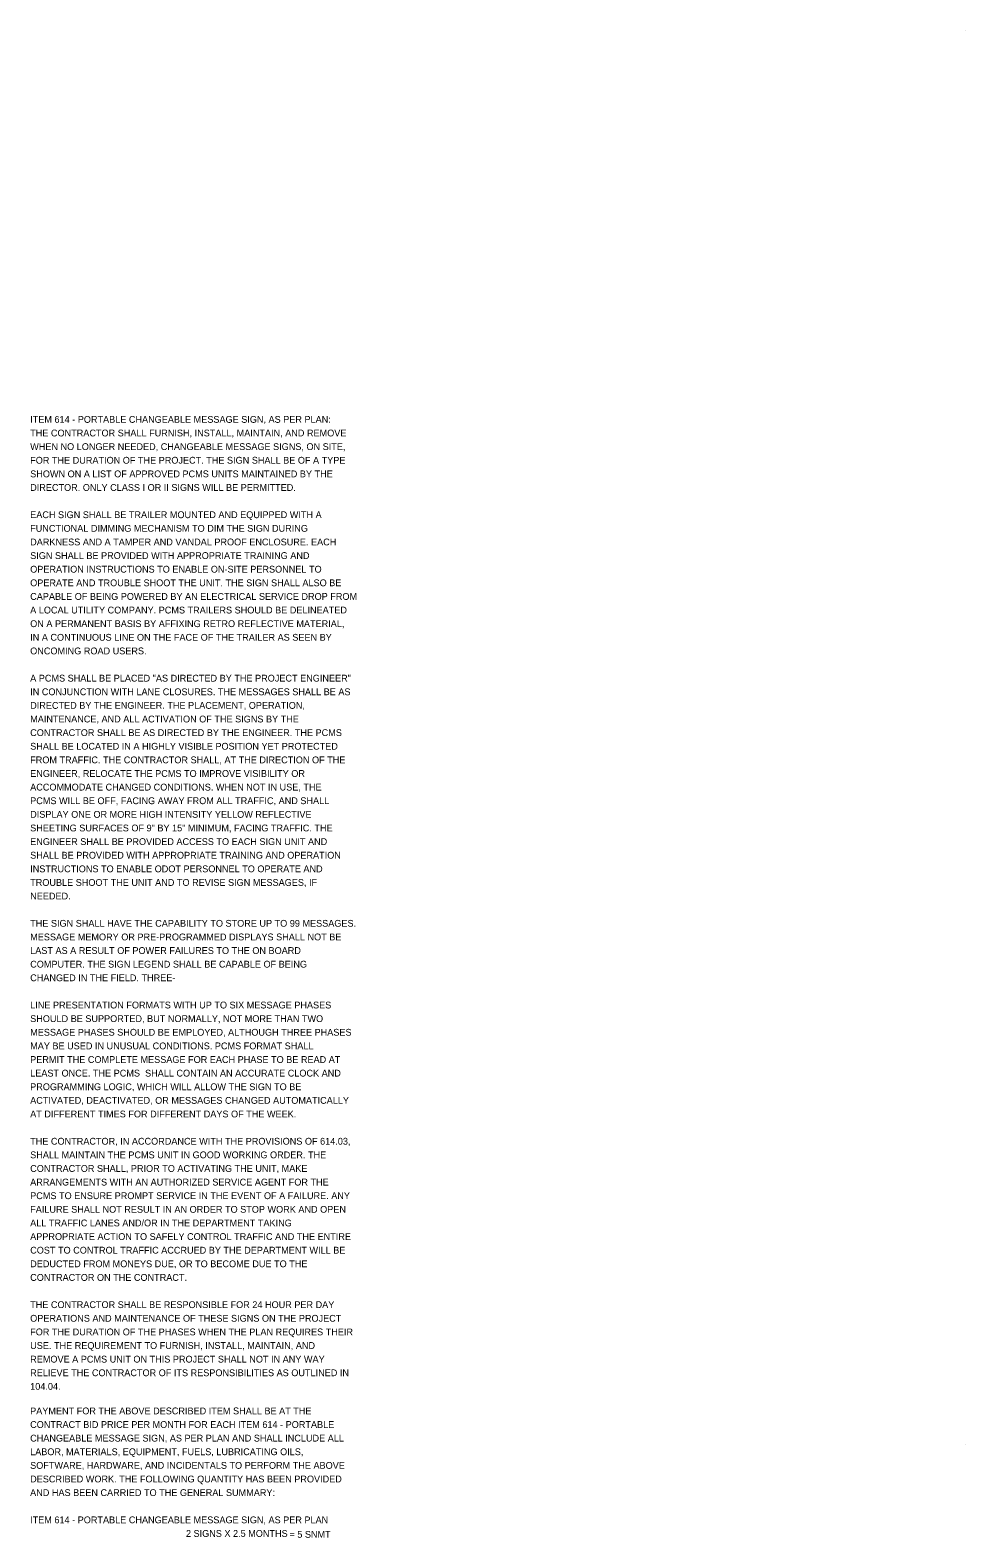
# Model space of a CAD drawing. Extents: x 37613.4 to 37668.4, y 18853.7 to 18946.8.
# Drawn here: x 37617.17 to 37636.4, y 18865.55 to 18896.54 of the extents above; entities that cross this region are included whole.
import ezdxf

# ---------------------------------------------------------------- set-up
doc = ezdxf.new("R2010")
doc.units = 0
doc.layers.add('SH_Data', color=7, linetype='Continuous')
doc.layers.add('SH_Text', color=7, linetype='Continuous')

msp = doc.modelspace()

# ---------------------------------------------------------------- linework, layer by layer
at = {"layer": 'SH_Data'}
for p, q in [((37636.401, 18896.542), (37636.401, 18896.542)), ((37636.401, 18867.47), (37636.401, 18867.47))]:
    msp.add_line(p, q, dxfattribs=at)

# ---------------------------------------------------------------- texts
at = {"layer": 'SH_Text'}
for s, p in [('ITEM 614 - PORTABLE CHANGEABLE MESSAGE SIGN, AS PER PLAN:', (37617.166, 18888.47)), ('THE CONTRACTOR SHALL FURNISH, INSTALL, MAINTAIN, AND REMOVE ', (37617.166, 18888.19)), ('WHEN NO LONGER NEEDED, CHANGEABLE MESSAGE SIGNS, ON SITE, ', (37617.166, 18887.91)), ('FOR THE DURATION OF THE PROJECT. THE SIGN SHALL BE OF A TYPE ', (37617.166, 18887.63)), ('SHOWN ON A LIST OF APPROVED PCMS UNITS MAINTAINED BY THE ', (37617.166, 18887.35)), ('DIRECTOR. ONLY CLASS I OR II SIGNS WILL BE PERMITTED.', (37617.166, 18887.07)), ('EACH SIGN SHALL BE TRAILER MOUNTED AND EQUIPPED WITH A ', (37617.166, 18886.51)), ('FUNCTIONAL DIMMING MECHANISM TO DIM THE SIGN DURING ', (37617.166, 18886.23)), ('DARKNESS AND A TAMPER AND VANDAL PROOF ENCLOSURE. EACH ', (37617.166, 18885.95)), ('SIGN SHALL BE PROVIDED WITH APPROPRIATE TRAINING AND ', (37617.166, 18885.67)), ('OPERATION INSTRUCTIONS TO ENABLE ON-SITE PERSONNEL TO ', (37617.166, 18885.39)), ('OPERATE AND TROUBLE SHOOT THE UNIT. THE SIGN SHALL ALSO BE ', (37617.166, 18885.11)), ('CAPABLE OF BEING POWERED BY AN ELECTRICAL SERVICE DROP FROM ', (37617.166, 18884.83)), ('A LOCAL UTILITY COMPANY. PCMS TRAILERS SHOULD BE DELINEATED ', (37617.166, 18884.55)), ('ON A PERMANENT BASIS BY AFFIXING RETRO REFLECTIVE MATERIAL, ', (37617.166, 18884.27)), ('IN A CONTINUOUS LINE ON THE FACE OF THE TRAILER AS SEEN BY ', (37617.166, 18883.99)), ('ONCOMING ROAD USERS.', (37617.166, 18883.71)), ('A PCMS SHALL BE PLACED "AS DIRECTED BY THE PROJECT ENGINEER" ', (37617.166, 18883.15)), ('IN CONJUNCTION WITH LANE CLOSURES. THE MESSAGES SHALL BE AS ', (37617.166, 18882.87)), ('DIRECTED BY THE ENGINEER. THE PLACEMENT, OPERATION, ', (37617.166, 18882.59)), ('MAINTENANCE, AND ALL ACTIVATION OF THE SIGNS BY THE ', (37617.166, 18882.31)), ('CONTRACTOR SHALL BE AS DIRECTED BY THE ENGINEER. THE PCMS ', (37617.166, 18882.03)), ('SHALL BE LOCATED IN A HIGHLY VISIBLE POSITION YET PROTECTED ', (37617.166, 18881.75)), ('FROM TRAFFIC. THE CONTRACTOR SHALL, AT THE DIRECTION OF THE ', (37617.166, 18881.47)), ('ENGINEER, RELOCATE THE PCMS TO IMPROVE VISIBILITY OR ', (37617.166, 18881.19)), ('ACCOMMODATE CHANGED CONDITIONS. WHEN NOT IN USE, THE ', (37617.166, 18880.91)), ('PCMS WILL BE OFF, FACING AWAY FROM ALL TRAFFIC, AND SHALL ', (37617.166, 18880.63)), ('DISPLAY ONE OR MORE HIGH INTENSITY YELLOW REFLECTIVE ', (37617.166, 18880.35)), ('SHEETING SURFACES OF 9" BY 15" MINIMUM, FACING TRAFFIC. THE ', (37617.166, 18880.07)), ('ENGINEER SHALL BE PROVIDED ACCESS TO EACH SIGN UNIT AND ', (37617.166, 18879.79)), ('SHALL BE PROVIDED WITH APPROPRIATE TRAINING AND OPERATION ', (37617.166, 18879.51)), ('INSTRUCTIONS TO ENABLE ODOT PERSONNEL TO OPERATE AND ', (37617.166, 18879.23)), ('TROUBLE SHOOT THE UNIT AND TO REVISE SIGN MESSAGES, IF ', (37617.166, 18878.95)), ('NEEDED.', (37617.166, 18878.67)), ('THE SIGN SHALL HAVE THE CAPABILITY TO STORE UP TO 99 MESSAGES. ', (37617.166, 18878.11)), ('MESSAGE MEMORY OR PRE-PROGRAMMED DISPLAYS SHALL NOT BE ', (37617.166, 18877.83)), ('LAST AS A RESULT OF POWER FAILURES TO THE ON BOARD ', (37617.166, 18877.55)), ('COMPUTER. THE SIGN LEGEND SHALL BE CAPABLE OF BEING ', (37617.166, 18877.27)), ('CHANGED IN THE FIELD. THREE-', (37617.166, 18876.99)), ('LINE PRESENTATION FORMATS WITH UP TO SIX MESSAGE PHASES ', (37617.166, 18876.43)), ('SHOULD BE SUPPORTED, BUT NORMALLY, NOT MORE THAN TWO ', (37617.166, 18876.15)), ('MESSAGE PHASES SHOULD BE EMPLOYED, ALTHOUGH THREE PHASES ', (37617.166, 18875.87)), ('MAY BE USED IN UNUSUAL CONDITIONS. PCMS FORMAT SHALL ', (37617.166, 18875.59)), ('PERMIT THE COMPLETE MESSAGE FOR EACH PHASE TO BE READ AT ', (37617.166, 18875.31)), ('LEAST ONCE. THE PCMS  SHALL CONTAIN AN ACCURATE CLOCK AND ', (37617.166, 18875.03)), ('PROGRAMMING LOGIC, WHICH WILL ALLOW THE SIGN TO BE ', (37617.166, 18874.75)), ('ACTIVATED, DEACTIVATED, OR MESSAGES CHANGED AUTOMATICALLY ', (37617.166, 18874.47)), ('AT DIFFERENT TIMES FOR DIFFERENT DAYS OF THE WEEK.', (37617.166, 18874.19)), ('THE CONTRACTOR, IN ACCORDANCE WITH THE PROVISIONS OF 614.03, ', (37617.166, 18873.63)), ('SHALL MAINTAIN THE PCMS UNIT IN GOOD WORKING ORDER. THE ', (37617.166, 18873.35)), ('CONTRACTOR SHALL, PRIOR TO ACTIVATING THE UNIT, MAKE ', (37617.166, 18873.07)), ('ARRANGEMENTS WITH AN AUTHORIZED SERVICE AGENT FOR THE ', (37617.166, 18872.79)), ('PCMS TO ENSURE PROMPT SERVICE IN THE EVENT OF A FAILURE. ANY ', (37617.166, 18872.51)), ('FAILURE SHALL NOT RESULT IN AN ORDER TO STOP WORK AND OPEN ', (37617.166, 18872.23)), ('ALL TRAFFIC LANES AND/OR IN THE DEPARTMENT TAKING ', (37617.166, 18871.95)), ('APPROPRIATE ACTION TO SAFELY CONTROL TRAFFIC AND THE ENTIRE ', (37617.166, 18871.67)), ('COST TO CONTROL TRAFFIC ACCRUED BY THE DEPARTMENT WILL BE ', (37617.166, 18871.39)), ('DEDUCTED FROM MONEYS DUE, OR TO BECOME DUE TO THE ', (37617.166, 18871.11)), ('CONTRACTOR ON THE CONTRACT.', (37617.166, 18870.83)), ('THE CONTRACTOR SHALL BE RESPONSIBLE FOR 24 HOUR PER DAY ', (37617.166, 18870.27)), ('OPERATIONS AND MAINTENANCE OF THESE SIGNS ON THE PROJECT ', (37617.166, 18869.99)), ('FOR THE DURATION OF THE PHASES WHEN THE PLAN REQUIRES THEIR ', (37617.166, 18869.71)), ('USE. THE REQUIREMENT TO FURNISH, INSTALL, MAINTAIN, AND ', (37617.166, 18869.43)), ('REMOVE A PCMS UNIT ON THIS PROJECT SHALL NOT IN ANY WAY ', (37617.166, 18869.15)), ('RELIEVE THE CONTRACTOR OF ITS RESPONSIBILITIES AS OUTLINED IN ', (37617.166, 18868.87)), ('104.04.', (37617.166, 18868.59)), ('PAYMENT FOR THE ABOVE DESCRIBED ITEM SHALL BE AT THE ', (37617.165, 18868.086)), ('CONTRACT BID PRICE PER MONTH FOR EACH ITEM 614 - PORTABLE ', (37617.165, 18867.806)), ('CHANGEABLE MESSAGE SIGN, AS PER PLAN AND SHALL INCLUDE ALL ', (37617.165, 18867.526)), ('LABOR, MATERIALS, EQUIPMENT, FUELS, LUBRICATING OILS, ', (37617.165, 18867.246)), ('SOFTWARE, HARDWARE, AND INCIDENTALS TO PERFORM THE ABOVE ', (37617.165, 18866.966)), ('AND HAS BEEN CARRIED TO THE GENERAL SUMMARY:', (37617.165, 18866.406)), ('DESCRIBED WORK. THE FOLLOWING QUANTITY HAS BEEN PROVIDED ', (37617.165, 18866.686)), ('ITEM 614 - PORTABLE CHANGEABLE MESSAGE SIGN, AS PER PLAN', (37617.165, 18865.846)), ('2 SIGNS X 2.5 MONTHS', (37620.368, 18865.566)), ('= 5 SNMT', (37622.496, 18865.548))]:
    msp.add_text(s, height=0.14, dxfattribs=at).set_placement(p)

doc.saveas('drawing.dxf')
